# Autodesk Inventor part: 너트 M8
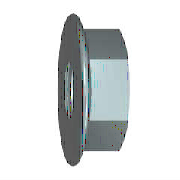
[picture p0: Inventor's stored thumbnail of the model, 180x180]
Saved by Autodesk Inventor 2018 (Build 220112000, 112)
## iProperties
Created: 2015-09
Part Number: 너트 M8
Material: 스테인리스강
Description: 플랜지붙이 6각 너트 - 일반 스레드
Document SubType Name: Modeling
Standard: ISO 4161
Designer: mduedu
Standard Revision: 2판 1999-03-15
Standards Organization: ISO
Language: ko-KR
Size Designation: M8
Categories: <MemberInstance><Categories><Category DisplayName="조임쇠" InternalName="e4da775c-781d-43d5-af7c-5136215cf5a6" Mnemonic="FSTN"><Category DisplayName="너트" InternalN
Density: 8.08 g/cm^3
Appearance: 기본값
Author: mduedu
IsCustomPart: 1
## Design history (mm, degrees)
sketch "스케치1"
  geometry: L1 (-1.844, 0)-(9.641, 0) reference; L2 (3.107, 6.5)-(2.288, 8.257); L3 (3.107, 6.5)-(8, 6.5); L4 (8, 6.5)-(8, 0); L5 (3.107, 6.5)-(3.107, 0); L6 (0, -1.835)-(0, 11.01) reference; A1 r 1.2 centre (1.2, 7.75) between (2.288, 8.257) and (0, 7.75); 1 further point
  constraints: 8 end point, 3 point on line, 2 perpendicular, 2 point on circle, 2 tangent, 1 centre point, 1 parallel
  dimensions: "d2" = 13 diameter of L3 L1 (= SW); "d4" = 17.9 dimension on A1 L1 (= LADI); "d5" = 1.2 radius of A1 (= PHH); "d15" = 8 distance between parallel lines of L4 L6 (= KOH); "d16" = 25 deg angle of L6 L2 (= KEWI)
revolve "링" sketch "스케치1" stored, may be unused: angle "d8" = 90 deg
sketch "스케치2"
  geometry: L1 (-6.5, -3.753)-(-6.5, 3.753); L2 (-6.5, 3.753)-(0, 7.506); L3 (0, 7.506)-(6.5, 3.753); L4 (6.5, 3.753)-(6.5, -3.753); L5 (6.5, -3.753)-(0, -7.506); L6 (0, -7.506)-(-6.5, -3.753); C1 r 4.9 at (0, 0); C2 r 7.75 at (0, 0) reference; 1 further point
  constraints: 12 end point, 1 centre point, 1 coincident, 1 vertical, 11 other
  dimensions: "d6" = 15.01111 distance of L5.end L2.end (= 1.1547 x SW)
extrude "본체" join sketch "스케치2" distance "d7" = 8 (= KOH); taper "d9" = 0 deg
sketch "스케치3"
  geometry: L1 (2.638, 7.506)-(8, 7.506) reference; L2 (8, 3.753)-(8, 7.506) reference; L3 (0, -7.75)-(0, 7.75) reference; L4 (-1.6, 0)-(9.6, 0) reference; L5 (7.419, 7.506)-(8, 6.5)
  constraints: 2 end point, 2 point on line
  dimensions: "d10" = 30 deg angle of L2 L5 (= ANG1); "d11" = 13 diameter of L5.end L4 (= SW0)
revolve "모따기1" sketch "스케치3" stored, may be unused: angle "d24" = 90 deg
sketch "스케치4"
  geometry: C1 r 7.75 at (0, 0) reference; 1 further point
  constraints: 1 coincident
hole "스레드" sketch "스케치4" at (0, 0) diameter "d25" = 6.647; stored, may be unused: countersink angle "d29" = 82 deg, drill point angle "d31" = 118 deg; dims "d26" = 6, "d27" = 4, "d28" = 2, "d30" = 8
workaxis "Work Axis1"
workplane "Work Plane1"
body "Solid1"
chamfer "모따기2" distance "d12" = 0.67658 (= -0.5 x GD1 + 0.5 x NND); stored, may be unused: angle "d13" = 30 deg, second distance "d46" = 0.67658 (= -0.5 x GD1 + 0.5 x NND)
chamfer "모따기3" distance "d51" = 0.67658 (= -0.5 x GD1 + 0.5 x NND); stored, may be unused: second distance "d52" = 2, angle "d53" = 45 deg
other parameters: "ANG1" = 30 deg [user parameter; used in 1 equation term], "KEWI" = 25 deg [user parameter; used in 1 equation term], "NND" = 8 [user parameter; used in 4 equation terms], "LADI" = 17.9 [user parameter; used in 2 equation terms], "SW" = 13 [user parameter; used in 3 equation terms], "PHH" = 1.2 [user parameter; used in 3 equation terms], "KOH" = 8 (= NND) [user parameter; used in 2 equation terms], "SW0" = 13 [user parameter; used in 1 equation term], "GD1" = 6.64684 (computed from THREADDIA, PTC, TOA) [user parameter; used in 3 equation terms], "d1" = 17.9 (= LADI), "d3" = 1.2 (= PHH), "d45" = 0, "d47" = 0, "d49" = 0, "d54" = 0, "GUL" = 0.67658 (= 0.541266 x PTC) [user parameter], "TPU" = 8 (computed from PTC) [user parameter], "RR" = 1.2 (= PHH) [user parameter], "THREADDIA" = 8 [user parameter; used in 1 equation term], "TOA" = 30 deg [user parameter; used in 1 equation term], "PTC" = 1.25 [user parameter; used in 4 equation terms], "GAL" = 0.67658 (= 0.541266 x PTC) [user parameter], "E0" = 15.015 (= 1.155 x SW) [user parameter]
